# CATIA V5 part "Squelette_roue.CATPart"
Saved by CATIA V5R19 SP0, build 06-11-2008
Part number: Squelette_roue
Bounding box of the stored display mesh (mm): x -500 to 500, y 2865.426 to 2865.426, z 329.578 to 329.578
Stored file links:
  C:\Users\Guillaume et Fanny\Documents\IFMA\2A\IAO\Squelette_roue.CATPart
  C:\Users\Guillaume et Fanny\Documents\IFMA\2A\IAO\Train d'aterrissage.CATProduct
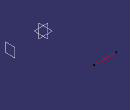
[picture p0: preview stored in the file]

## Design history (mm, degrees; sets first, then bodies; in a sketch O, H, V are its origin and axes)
Set1
  Point1: linked copy from another document
Body1 (main body)
  Line1: type PtDir, Direction (1, 0, 0), Start -500, End 500, RefPoint Point1
  Plane1: type Offset, Offset 1520, RefPlane yz-plane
